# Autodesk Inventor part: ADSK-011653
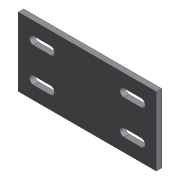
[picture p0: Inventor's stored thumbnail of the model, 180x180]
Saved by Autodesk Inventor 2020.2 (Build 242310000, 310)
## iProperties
Created: 2000-02
Part Number: ADSK-011653
Material: Pearson HRS
Document SubType Name: Modeling
Designer: sspink
Density: 7.83 g/cm^3
Appearance: Métal - Acier
Mass: 500.409 g
Surface Area: 256.356 cm^2
Volume: 63.9092 cm^3
Control State: 0
Checked Out: False
Master: False
Shininess: 0.0
Length Units: 11269
Angle Units: 11279
Time Units: 11290
Mass Units: 11283
Length Display Precision: 3
Angle Display Precision: 2
Compacted: True
Cutlength: 6
Material Desc: FLAT,HRS,0.250X03.000
Material_Number: A084336
Dimensions: 76x6x152,5 mm
Mass: 0,5 kg
VLT_Material: Pearson HRS
Density: 0.0
Volumn: 0.0
Area: 0.0
PropertySet Name: Model Information
Author: sspink
Revision Number: -
Title: ADSK-011653
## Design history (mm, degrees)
node "Solide1"
  node "Extrusion1" dims "d2" = 6, "d3" = 0
  node "Extrusion2" dims "d12" = 25.4, "d13" = 0
  node "Chamfer1" dims "d14" = 6, "d15" = 42 deg, "d16" = 5.95312
sketch "Sketch1"
  geometry: L1 (-76.25, -38)-(76.25, -38); L2 (76.25, -38)-(76.25, 38); L3 (76.25, 38)-(-76.25, 38); L4 (-76.25, 38)-(-76.25, -38); 3 further points
  constraints: 8 end point, 2 midpoint, 2 parallel, 1 horizontal, 1 horizontal alignment, 1 perpendicular, 1 vertical alignment
  dimensions: "d0" = 76 distance between parallel lines of L3 L1; "d1" = 152.5 distance between parallel lines of L2 L4
sketch "Sketch2"
  geometry: L1 (76.25, -38)-(-76.25, -38) reference; L2 (76.25, 38)-(76.25, -38) reference; L3 (-59.5, 23.5)-(-40.5, 23.5); L4 (-40.5, 23.5)-(-40.5, 14.5); L5 (-40.5, 14.5)-(-59.5, 14.5); L6 (-59.5, 14.5)-(-59.5, 23.5); L7 (-59.5, -14.5)-(-40.5, -14.5); L8 (-40.5, -14.5)-(-40.5, -23.5); L9 (-40.5, -23.5)-(-59.5, -23.5); L10 (-59.5, -23.5)-(-59.5, -14.5); L11 (40.5, 23.5)-(59.5, 23.5); L12 (59.5, 23.5)-(59.5, 14.5); L13 (59.5, 14.5)-(40.5, 14.5); L14 (40.5, 14.5)-(40.5, 23.5); L15 (40.5, -14.5)-(59.5, -14.5); L16 (59.5, -14.5)-(59.5, -23.5); L17 (59.5, -23.5)-(40.5, -23.5); L18 (40.5, -23.5)-(40.5, -14.5); L19 (59.5, -19)-(40.5, -19); L20 (-40.5, -19)-(-59.5, -19); L21 (59.5, 19)-(40.5, 19); L22 (-40.5, 19)-(-59.5, 19); L23 (50, -19)-(-50, -19); L24 (-50, -19)-(-50, 19); L25 (-50, 19)-(50, 19); L26 (50, 19)-(50, -19); A1 r 4.5 centre (-40.5, 19) between (-40.5, 14.5) and (-40.5, 23.5); A2 r 4.5 centre (-59.5, 19) between (-59.5, 23.5) and (-59.5, 14.5); A3 r 4.5 centre (-59.5, -19) between (-59.5, -14.5) and (-59.5, -23.5); A4 r 4.5 centre (-40.5, -19) between (-40.5, -23.5) and (-40.5, -14.5); A5 r 4.5 centre (40.5, 19) between (40.5, 23.5) and (40.5, 14.5); A6 r 4.5 centre (59.5, 19) between (59.5, 14.5) and (59.5, 23.5); A7 r 4.5 centre (40.5, -19) between (40.5, -14.5) and (40.5, -23.5); A8 r 4.5 centre (59.5, -19) between (59.5, -23.5) and (59.5, -14.5); 4 further points
  constraints: 48 end point, 16 point on circle, 10 parallel, 8 centre point, 8 midpoint, 8 tangent, 7 equal length, 6 horizontal, 5 perpendicular, 3 vertical alignment, 1 horizontal alignment
  dimensions: "d4" = 19 distance of L4.end L5.end; "d5" = 9 distance of L3.end L4.end; "d17" = 38 distance of L25.end L23.start; "d18" = 100 distance of L23.start L23.end
workpoint "Arbeitspunkt1"
workpoint "Arbeitspunkt2"
workpoint "Arbeitspunkt3"
workpoint "Arbeitspunkt4"
workaxis "Arbeitsachse1"
workaxis "Arbeitsachse2"
workaxis "Arbeitsachse3"
workaxis "Arbeitsachse4"
node "Corps solides"
node "Corps surfaciques"
